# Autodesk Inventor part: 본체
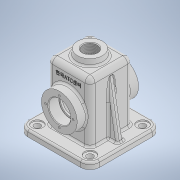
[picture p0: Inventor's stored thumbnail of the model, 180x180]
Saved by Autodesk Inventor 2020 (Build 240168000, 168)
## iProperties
Created: 2021-07
Part Number: 본체
Material: 일반
Document SubType Name: Modeling
Designer: Owner
Density: 1 g/cm^3
Appearance: 기본값
Mass: 270.432 g
Surface Area: 855.313 cm^2
Volume: 270.432 cm^3
Author: Owner
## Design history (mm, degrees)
sketch "스케치1"
  geometry: L1 (-57, 57)-(57, 57); L2 (57, 57)-(57, -57); L3 (57, -57)-(-57, -57); L4 (-57, -57)-(-57, 57); L5 (-57, 57)-(57, -57); L6 (57, 57)-(-57, -57); 1 further point
  constraints: 12 end point, 2 midpoint, 2 parallel, 1 horizontal, 1 perpendicular
  dimensions: "d0" = 114 distance of L2.end L3.end; "d1" = 114 distance of L1.end L2.end
extrude "돌출1" new body sketch "스케치1" distance "d2" = 10; taper "d3" = 0 deg
fillet "모깎기1" dims "d4" = 15
sketch "스케치2"
  geometry: A1 r 15 centre (-42, 42) between (-42, 57) and (-57, 42) reference; 2 further points
  constraints: 1 coincident
hole "구멍1" sketch "스케치2" at (-42, 42) diameter "d5" = 10; stored, may be unused: countersink angle "d9" = 90 deg, drill point angle "d11" = 0 deg; dims "d6" = 30, "d7" = 18, "d8" = 2, "d10" = 10
sketch "스케치3"
  geometry: L1 (34, -34)-(-34, -34); L2 (-34, -34)-(-34, 34); L3 (-34, 34)-(34, 34); L4 (34, 34)-(34, -34); L5 (34, -34)-(-34, 34); L6 (-34, -34)-(34, 34); 1 further point
  constraints: 12 end point, 2 midpoint, 2 parallel, 1 horizontal, 1 perpendicular
  dimensions: "d12" = 68 distance of L2.end L3.end; "d13" = 68 distance of L1.end L2.end
extrude "돌출2" join sketch "스케치3" distance "d14" = 95; taper "d15" = 0 deg
sketch "스케치4"
  geometry: L1 (29, 29)-(-29, 29); L2 (-29, 29)-(-29, -29); L3 (-29, -29)-(29, -29); L4 (29, -29)-(29, 29); L5 (29, 29)-(-29, -29); L6 (-29, 29)-(29, -29); 1 further point
  constraints: 12 end point, 2 midpoint, 2 parallel, 1 horizontal, 1 perpendicular
  dimensions: "d16" = 58 distance of L1.end L2.end; "d17" = 58 distance of L2.end L3.end
extrude "돌출3" cut sketch "스케치4" distance "d18" = 100; taper "d19" = 0 deg
sketch "스케치5"
  geometry: L1 (-8, -10)-(76, -10) reference; L2 (0, 0)-(0, 95) reference; C1 r 28.5 at (34, 42); 1 further point
  constraints: 1 centre point
  dimensions: "d20" = 57 diameter of C1; "d21" = 52 distance from line of L1 C1.centre; "d22" = 34 distance from line of L2 C1.centre
extrude "돌출4" join sketch "스케치5" distance "d23" = 15; taper "d24" = 0 deg
sketch "스케치6"
  geometry: C1 r 28.5 at (0, 0) reference; 2 further points
  constraints: 1 coincident
hole "구멍2" sketch "스케치6" at (0, 0) diameter "d25" = 35; stored, may be unused: countersink angle "d29" = 90 deg, drill point angle "d31" = 0 deg; dims "d26" = 30, "d27" = 18, "d28" = 2, "d30" = 17
sketch "스케치7"
  geometry: C1 r 17.5 at (0, 0) reference; 2 further points
  constraints: 1 coincident
hole "구멍3" sketch "스케치7" at (0, 0) diameter "d32" = 30; stored, may be unused: countersink angle "d36" = 90 deg, drill point angle "d38" = 0 deg; dims "d33" = 30, "d34" = 18, "d35" = 2, "d37" = 3
fillet "모깎기2" dims "d39" = 8
node "작업 평면1"
sketch "스케치8"
  geometry: C1 r 20 at (0, 0); 1 further point
  constraints: 1 centre point, 1 coincident
  dimensions: "d41" = 40 diameter of C1
extrude "돌출5" join sketch "스케치8" stored distance "d42" = 15; taper "d43" = 8 deg
sketch "스케치9"
  geometry: C1 r 20 at (0, 0) reference; 2 further points
  constraints: 1 coincident
hole "구멍4" sketch "스케치9" at (0, 0) diameter "d44" = 22.83494; stored, may be unused: countersink angle "d48" = 82 deg, drill point angle "d50" = 0 deg; dims "d45" = 50, "d46" = 3.023, "d47" = 2, "d49" = 59.3
sketch "스케치10"
  geometry: L1 (-35.139, 88.612)-(-49, 10); L2 (-57, 10)-(-42, 10) reference; L3 (-57, 0)-(-57, 10) reference; 1 further point
  constraints: 2 end point, 1 point on line
  dimensions: "d51" = 10 deg angle of L3 L1; "d52" = 8 distance of L1.end L2.start
feature "리브1" sketch "스케치10" dims "d53" = 1, "d54" = 10, "d55" = 0, "d56" = 0, "d57" = 1, "d58" = 1
sketch "스케치11"
  geometry: L1 (-34, 45)-(-34, -42) reference; C1 r 28.5 at (0, 0) reference; 2 further points
  dimensions: "d59" = 22 distance of C1.centre point (0, 22); "d60" = 34 distance from line of L1 point (0, 22)
hole "구멍5" sketch "스케치11" at (0, 22) diameter "d61" = 3.242; stored, may be unused: countersink angle "d65" = 82 deg, drill point angle "d67" = 118 deg; dims "d62" = 8, "d63" = 3.023, "d64" = 2, "d66" = 10
sketch "스케치12"
  geometry: L1 (20, 63)-(-20, 63) reference; L2 (-34, 45)-(-34, -42) reference; 2 further points
  constraints: 1 other
  dimensions: "d71" = 25 distance from line of L1 point (0, 38); "d72" = 34 distance from line of L2 point (0, 38)
feature "엠보싱1" sketch "스케치12" dims "d73" = 0.5, "d74" = 0
chamfer "모따기1" distance "d75" = 1; stored, may be unused: second distance "d76" = 2, angle "d77" = 45 deg
fillet "모깎기3" dims "d78" = 3
fillet "모깎기4" dims "d79" = 3
fillet "모깎기5" dims "d80" = 3
fillet "모깎기6" dims "d81" = 3
fillet "모깎기7" dims "d82" = 3
fillet "모깎기8" dims "d83" = 0.3
node "솔리드1"
mirror "미러1"
mirror "미러2"
mirror "미러3"
mirror "미러4"
mirror "미러5"
mirror "미러6"
pattern_circular "원형 패턴1" dims angle "d69" = 360 deg
mirror "미러7"
feature "A9D066F2-1C7D-4E18-AEED-F7BC21143FA4" dims "d5" = 10, "d6" = 30, "d7" = 18, "d8" = 2, "d9" = 90 deg, "d10" = 10, "d11" = 0
